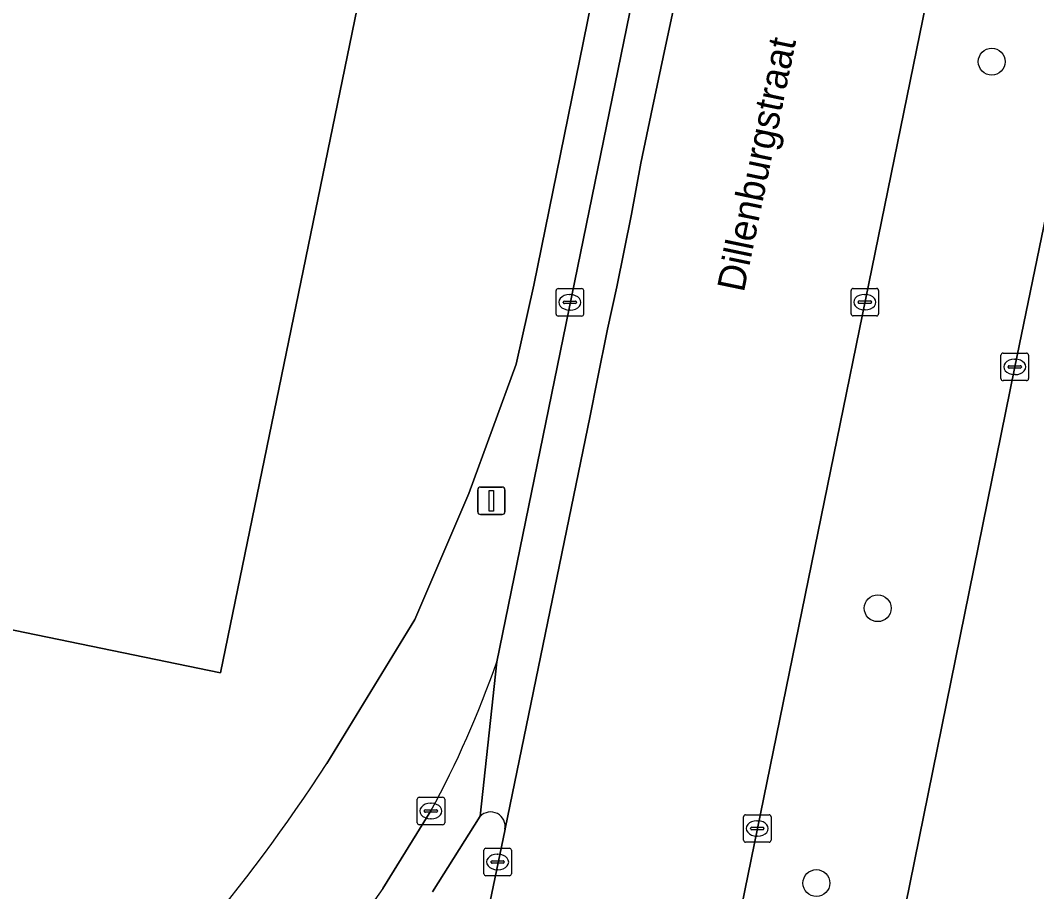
# Model space of a CAD drawing. Extents: x 157692 to 159674, y 381452 to 383291.
# Drawn here: x 158498.72 to 158535.67, y 382148.13 to 382179.81 of the extents above; entities that cross this region are included whole.
import ezdxf

# ---------------------------------------------------------------- set-up
doc = ezdxf.new("R2010")
doc.units = 0
for name, color, linetype in [('IMGEO_Berm_groen', 7, 'Continuous'), ('IMGEO_Boom', 7, 'Continuous'), ('IMGEO_Erf', 7, 'Continuous'), ('IMGEO_Fietspad_gesloten', 7, 'Continuous'), ('IMGEO_Kolk', 7, 'Continuous'), ('IMGEO_Lichtmast', 7, 'Continuous'), ('IMGEO_Openbare_ruimte_label', 7, 'Continuous'), ('IMGEO_Pand', 7, 'Continuous'), ('IMGEO_Rijbaan_lokaal_gesloten', 7, 'Continuous'), ('IMGEO_Verkeerseiland_groen', 7, 'Continuous'), ('IMGEO_Voetpad_open', 7, 'Continuous')]:
    doc.layers.add(name, color=color, linetype=linetype)

msp = doc.modelspace()

# ---------------------------------------------------------------- linework, layer by layer
at = {"layer": 'IMGEO_Berm_groen'}
for points in [[(158566.644, 382322.187), (158567.234, 382325.064), (158567.304, 382325.746), (158567.225, 382326.384), (158567.068, 382326.86), (158566.787, 382327.371), (158566.493, 382327.735), (158566.011, 382328.143), (158565.497, 382328.42), (158565.051, 382328.557), (158564.939, 382328.591), (158564.425, 382328.647), (158563.854, 382328.604), (158563.281, 382328.442), (158562.742, 382328.162), (158562.266, 382327.772), (158561.897, 382327.314), (158561.609, 382326.746), (158561.45, 382326.139), (158553.124, 382285.066), (158549.349, 382267.06), (158522.982, 382137.975)], [(158528.747, 382136.998), (158534.877, 382167.21), (158542.075, 382202.135), (158547.202, 382227.455), (158566.644, 382322.187)]]:
    msp.add_lwpolyline(points, dxfattribs=at)
at = {"layer": 'IMGEO_Boom'}
for centre in [(158534.04, 382178.306), (158529.896, 382158.438), (158527.666, 382148.444)]:
    msp.add_circle(centre, 0.489, dxfattribs=at)
at = {"layer": 'IMGEO_Erf'}
for points in [[(158509.861, 382152.794), (158513.065, 382158.027), (158515.032, 382162.604), (158516.746, 382167.312), (158517.398, 382170.178), (158524.332, 382204.307), (158524.967, 382207.431), (158524.987, 382207.53), (158526.326, 382214.089), (158527.009, 382217.437), (158528.187, 382223.205), (158528.445, 382224.468), (158549.165, 382325.299), (158550.563, 382332.1), (158550.799, 382333.648), (158551.524, 382338.412)], [(158464.768, 382230.207), (158518.944, 382219.046), (158505.997, 382156.09), (158482, 382161.038), (158467.988, 382163.933), (158454.893, 382166.763)]]:
    msp.add_lwpolyline(points, dxfattribs=at)
msp.add_arc((158459.249, 382185.395), 60.203, 311.86075, 327.21256, dxfattribs=at)
at = {"layer": 'IMGEO_Fietspad_gesloten'}
for points in [[(158513.708, 382148.133), (158515.441, 382150.872), (158516.046, 382156.484)], [(158513.651, 382151.066), (158511.906, 382148.246)]]:
    msp.add_lwpolyline(points, dxfattribs=at)
for centre, radius, start, end in [((158481.088, 382168.699), 37.03, 331.5647, 340.7401), ((158524.385, 382139.071), 15.489, 143.6738, 173.4818)]:
    msp.add_arc(centre, radius, start, end, dxfattribs=at)
at = {"layer": 'IMGEO_Kolk'}
for p, q in [((158518.203, 382169.132), (158518.203, 382169.984)), ((158518.278, 382170.058), (158519.13, 382170.058)), ((158519.204, 382169.984), (158519.204, 382169.132)), ((158528.926, 382169.138), (158528.926, 382169.99)), ((158529.001, 382170.064), (158529.853, 382170.064)), ((158529.927, 382169.99), (158529.927, 382169.138)), ((158518.462, 382169.552), (158518.462, 382169.564)), ((158518.9, 382169.515), (158518.502, 382169.515)), ((158518.505, 382169.601), (158518.903, 382169.601)), ((158518.691, 382169.838), (158518.716, 382169.838)), ((158518.946, 382169.564), (158518.946, 382169.552)), ((158529.185, 382169.558), (158529.185, 382169.57)), ((158529.623, 382169.521), (158529.225, 382169.521)), ((158529.228, 382169.607), (158529.626, 382169.607)), ((158529.414, 382169.844), (158529.439, 382169.844)), ((158529.669, 382169.57), (158529.669, 382169.558)), ((158518.714, 382169.278), (158518.689, 382169.278)), ((158529.437, 382169.284), (158529.412, 382169.284)), ((158519.13, 382169.058), (158518.278, 382169.058)), ((158529.853, 382169.064), (158529.001, 382169.064)), ((158534.376, 382166.784), (158534.376, 382167.636)), ((158534.451, 382167.71), (158535.303, 382167.71)), ((158535.377, 382167.636), (158535.377, 382166.784)), ((158534.864, 382167.49), (158534.889, 382167.49)), ((158534.635, 382167.204), (158534.635, 382167.216)), ((158535.073, 382167.167), (158534.675, 382167.167)), ((158534.678, 382167.253), (158535.076, 382167.253)), ((158534.887, 382166.93), (158534.862, 382166.93)), ((158535.119, 382167.216), (158535.119, 382167.204)), ((158535.303, 382166.71), (158534.451, 382166.71)), ((158513.15, 382150.64), (158513.15, 382151.492)), ((158513.225, 382151.566), (158514.077, 382151.566)), ((158514.151, 382151.492), (158514.151, 382150.64)), ((158513.409, 382151.06), (158513.409, 382151.072)), ((158513.847, 382151.023), (158513.449, 382151.023)), ((158513.452, 382151.109), (158513.85, 382151.109)), ((158513.638, 382151.346), (158513.663, 382151.346)), ((158513.893, 382151.072), (158513.893, 382151.06)), ((158513.661, 382150.786), (158513.636, 382150.786)), ((158525.016, 382150.004), (158525.016, 382150.856)), ((158525.091, 382150.93), (158525.943, 382150.93)), ((158525.504, 382150.71), (158525.529, 382150.71)), ((158526.017, 382150.856), (158526.017, 382150.004)), ((158514.077, 382150.566), (158513.225, 382150.566)), ((158525.275, 382150.424), (158525.275, 382150.436)), ((158525.713, 382150.387), (158525.315, 382150.387)), ((158525.318, 382150.473), (158525.716, 382150.473)), ((158525.759, 382150.436), (158525.759, 382150.424)), ((158525.943, 382149.93), (158525.091, 382149.93)), ((158525.527, 382150.15), (158525.502, 382150.15)), ((158515.576, 382148.785), (158515.576, 382149.637)), ((158515.651, 382149.711), (158516.503, 382149.711)), ((158516.577, 382149.637), (158516.577, 382148.785)), ((158515.835, 382149.205), (158515.835, 382149.217)), ((158516.273, 382149.168), (158515.875, 382149.168)), ((158515.878, 382149.254), (158516.276, 382149.254)), ((158516.064, 382149.491), (158516.089, 382149.491)), ((158516.319, 382149.217), (158516.319, 382149.205)), ((158516.087, 382148.931), (158516.062, 382148.931)), ((158516.503, 382148.711), (158515.651, 382148.711))]:
    msp.add_line(p, q, dxfattribs=at)
for points in [[(158518.203, 382169.132), (158518.203, 382169.984)], [(158518.278, 382170.058), (158519.13, 382170.058)], [(158519.204, 382169.984), (158519.204, 382169.132)], [(158528.926, 382169.138), (158528.926, 382169.99)], [(158529.001, 382170.064), (158529.853, 382170.064)], [(158529.927, 382169.99), (158529.927, 382169.138)], [(158519.13, 382169.058), (158518.278, 382169.058)], [(158529.853, 382169.064), (158529.001, 382169.064)], [(158534.376, 382166.784), (158534.376, 382167.636)], [(158534.451, 382167.71), (158535.303, 382167.71)], [(158535.377, 382167.636), (158535.377, 382166.784)], [(158535.303, 382166.71), (158534.451, 382166.71)], [(158513.15, 382150.64), (158513.15, 382151.492)], [(158513.225, 382151.566), (158514.077, 382151.566)], [(158514.151, 382151.492), (158514.151, 382150.64)], [(158525.016, 382150.004), (158525.016, 382150.856)], [(158525.091, 382150.93), (158525.943, 382150.93)], [(158526.017, 382150.856), (158526.017, 382150.004)], [(158514.077, 382150.566), (158513.225, 382150.566)], [(158525.943, 382149.93), (158525.091, 382149.93)], [(158515.576, 382148.785), (158515.576, 382149.637)], [(158515.651, 382149.711), (158516.503, 382149.711)], [(158516.577, 382149.637), (158516.577, 382148.785)], [(158516.503, 382148.711), (158515.651, 382148.711)]]:
    msp.add_lwpolyline(points, dxfattribs=at)
for centre, radius, start, end in [((158518.28, 382169.982), 0.0765, 91.552, 178.448), ((158518.28, 382169.982), 0.0765, 91.552, 178.448), ((158519.128, 382169.982), 0.0765, 1.552, 88.448), ((158519.128, 382169.982), 0.0765, 1.552, 88.448), ((158529.003, 382169.988), 0.0765, 91.552, 178.448), ((158529.003, 382169.988), 0.0765, 91.552, 178.448), ((158529.851, 382169.988), 0.0765, 1.552, 88.448), ((158529.851, 382169.988), 0.0765, 1.552, 88.448), ((158518.502, 382169.561), 0.0403, 85.8775, 175.7526), ((158518.499, 382169.551), 0.0366, 178.938, 274.7102), ((158518.903, 382169.558), 0.043, 264.8664, 352.4533), ((158518.907, 382169.563), 0.0386, 1.7309, 96.639), ((158529.225, 382169.567), 0.0403, 85.8775, 175.7526), ((158529.222, 382169.557), 0.0366, 178.938, 274.7102), ((158529.626, 382169.564), 0.043, 264.8664, 352.4533), ((158529.63, 382169.569), 0.0386, 1.7309, 96.639), ((158518.28, 382169.134), 0.0765, 181.552, 268.448), ((158518.28, 382169.134), 0.0765, 181.552, 268.448), ((158519.128, 382169.134), 0.0765, 271.552, 358.448), ((158519.128, 382169.134), 0.0765, 271.552, 358.448), ((158529.003, 382169.14), 0.0765, 181.552, 268.448), ((158529.003, 382169.14), 0.0765, 181.552, 268.448), ((158529.851, 382169.14), 0.0765, 271.552, 358.448), ((158529.851, 382169.14), 0.0765, 271.552, 358.448), ((158534.453, 382167.634), 0.0765, 91.552, 178.448), ((158534.453, 382167.634), 0.0765, 91.552, 178.448), ((158535.301, 382167.634), 0.0765, 1.552, 88.448), ((158535.301, 382167.634), 0.0765, 1.552, 88.448), ((158534.675, 382167.213), 0.0403, 85.8775, 175.7526), ((158534.672, 382167.203), 0.0366, 178.938, 274.7102), ((158535.076, 382167.21), 0.043, 264.8664, 352.4533), ((158535.08, 382167.215), 0.0386, 1.7309, 96.639), ((158534.453, 382166.786), 0.0765, 181.552, 268.448), ((158534.453, 382166.786), 0.0765, 181.552, 268.448), ((158535.301, 382166.786), 0.0765, 271.552, 358.448), ((158535.301, 382166.786), 0.0765, 271.552, 358.448), ((158513.227, 382151.49), 0.0765, 91.552, 178.448), ((158513.227, 382151.49), 0.0765, 91.552, 178.448), ((158514.075, 382151.49), 0.0765, 1.552, 88.448), ((158514.075, 382151.49), 0.0765, 1.552, 88.448), ((158513.449, 382151.069), 0.0403, 85.8775, 175.7526), ((158513.446, 382151.059), 0.0366, 178.938, 274.7102), ((158513.85, 382151.066), 0.043, 264.8664, 352.4533), ((158513.854, 382151.071), 0.0386, 1.7309, 96.639), ((158513.227, 382150.642), 0.0765, 181.552, 268.448), ((158513.227, 382150.642), 0.0765, 181.552, 268.448), ((158514.075, 382150.642), 0.0765, 271.552, 358.448), ((158514.075, 382150.642), 0.0765, 271.552, 358.448), ((158525.093, 382150.854), 0.0765, 91.552, 178.448), ((158525.093, 382150.854), 0.0765, 91.552, 178.448), ((158525.941, 382150.854), 0.0765, 1.552, 88.448), ((158525.941, 382150.854), 0.0765, 1.552, 88.448), ((158525.315, 382150.433), 0.0403, 85.8775, 175.7526), ((158525.312, 382150.423), 0.0366, 178.938, 274.7102), ((158525.716, 382150.43), 0.043, 264.8664, 352.4533), ((158525.72, 382150.435), 0.0386, 1.7309, 96.639), ((158525.093, 382150.006), 0.0765, 181.552, 268.448), ((158525.093, 382150.006), 0.0765, 181.552, 268.448), ((158525.941, 382150.006), 0.0765, 271.552, 358.448), ((158525.941, 382150.006), 0.0765, 271.552, 358.448), ((158515.653, 382149.635), 0.0765, 91.552, 178.448), ((158515.653, 382149.635), 0.0765, 91.552, 178.448), ((158516.501, 382149.635), 0.0765, 1.552, 88.448), ((158516.501, 382149.635), 0.0765, 1.552, 88.448), ((158515.875, 382149.214), 0.0403, 85.8775, 175.7526), ((158515.872, 382149.204), 0.0366, 178.938, 274.7102), ((158516.276, 382149.211), 0.043, 264.8664, 352.4533), ((158516.28, 382149.216), 0.0386, 1.7309, 96.639), ((158515.653, 382148.787), 0.0765, 181.552, 268.448), ((158515.653, 382148.787), 0.0765, 181.552, 268.448), ((158516.501, 382148.787), 0.0765, 271.552, 358.448), ((158516.501, 382148.787), 0.0765, 271.552, 358.448)]:
    msp.add_arc(centre, radius, start, end, dxfattribs=at)
for centre, major_axis, ratio, start_param, end_param in [((158518.69, 382169.558), (-0.387, 0.002), 0.722429, 4.712389, 7.853982), ((158518.715, 382169.558), (-0.39, 0.002), 0.717154, 1.570796, 4.712389), ((158529.413, 382169.564), (-0.387, 0.002), 0.722429, 4.712389, 7.853982), ((158529.438, 382169.564), (-0.39, 0.002), 0.717154, 1.570796, 4.712389), ((158534.863, 382167.21), (-0.387, 0.002), 0.722429, 4.712389, 7.853982), ((158534.888, 382167.21), (-0.39, 0.002), 0.717154, 1.570796, 4.712389), ((158513.637, 382151.066), (-0.387, 0.002), 0.722429, 4.712389, 7.853982), ((158513.662, 382151.066), (-0.39, 0.002), 0.717154, 1.570796, 4.712389), ((158525.503, 382150.43), (-0.387, 0.002), 0.722429, 4.712389, 7.853982), ((158525.528, 382150.43), (-0.39, 0.002), 0.717154, 1.570796, 4.712389), ((158516.063, 382149.211), (-0.387, 0.002), 0.722429, 4.712389, 7.853982), ((158516.088, 382149.211), (-0.39, 0.002), 0.717154, 1.570796, 4.712389)]:
    msp.add_ellipse(centre, major_axis=major_axis, ratio=ratio, start_param=start_param, end_param=end_param, dxfattribs=at)
at = {"layer": 'IMGEO_Lichtmast'}
for p, q in [((158515.453, 382162.844), (158516.243, 382162.844)), ((158516.243, 382162.844), (158515.453, 382162.844)), ((158515.353, 382161.944), (158515.353, 382162.744)), ((158515.353, 382162.744), (158515.353, 382161.944)), ((158516.343, 382162.744), (158516.343, 382161.944)), ((158516.343, 382161.944), (158516.343, 382162.744)), ((158516.243, 382161.844), (158515.453, 382161.844)), ((158515.453, 382161.844), (158516.243, 382161.844))]:
    msp.add_line(p, q, dxfattribs=at)
msp.add_lwpolyline([(158515.773, 382162.719), (158515.923, 382162.719), (158515.923, 382161.969), (158515.773, 382161.969), (158515.773, 382162.719)], dxfattribs=at)
for centre, start, end in [((158515.453, 382162.744), 90, 180), ((158515.453, 382162.744), 90, 180), ((158516.243, 382162.744), 0, 90), ((158516.243, 382162.744), 360, 90), ((158515.453, 382161.944), 180, 270), ((158515.453, 382161.944), 180, 270), ((158516.243, 382161.944), 270, 0), ((158516.243, 382161.944), 270, 0)]:
    msp.add_arc(centre, 0.1, start, end, dxfattribs=at)
at = {"layer": 'IMGEO_Pand'}
msp.add_lwpolyline([(158454.893, 382166.763), (158467.988, 382163.933), (158482, 382161.038), (158505.997, 382156.09), (158518.944, 382219.046), (158464.768, 382230.207)], dxfattribs=at)
at = {"layer": 'IMGEO_Rijbaan_lokaal_gesloten'}
for points in [[(158566.717, 382304.975), (158570.119, 382321.454), (158566.644, 382322.187), (158547.202, 382227.455), (158542.075, 382202.135), (158534.877, 382167.21), (158528.747, 382136.998), (158534.64, 382136.161), (158544.988, 382186.707), (158554.178, 382231.666)], [(158522.982, 382137.975), (158549.349, 382267.06)], [(158516.345, 382150.4), (158516.351, 382150.416), (158519.44, 382165.43), (158519.695, 382166.711), (158520.067, 382168.58), (158520.406, 382170.124), (158520.949, 382172.76), (158521.285, 382174.615), (158521.711, 382176.637), (158522.095, 382178.467), (158522.54, 382180.58), (158522.925, 382182.414), (158523.324, 382184.31), (158523.361, 382184.485), (158523.847, 382186.302), (158524.097, 382187.038), (158524.398, 382187.848), (158525.073, 382189.43), (158525.289, 382189.937), (158525.428, 382190.17), (158526.611, 382192.236), (158527.621, 382193.95), (158528.593, 382195.516), (158541.544, 382258.661)], [(158525.939, 382194.629), (158522.444, 382187.753), (158516.046, 382156.484), (158515.441, 382150.872)], [(158522.54, 382180.58), (158522.095, 382178.467), (158521.711, 382176.637), (158521.285, 382174.615), (158520.949, 382172.76), (158520.406, 382170.124), (158520.067, 382168.58), (158519.695, 382166.711), (158519.44, 382165.43), (158516.351, 382150.416), (158516.345, 382150.4), (158514.093, 382139.59)]]:
    msp.add_lwpolyline(points, dxfattribs=at)
msp.add_arc((158515.82, 382150.497), 0.533, 349.5318, 135.3279, dxfattribs=at)
at = {"layer": 'IMGEO_Verkeerseiland_groen'}
for points in [[(158515.441, 382150.872), (158513.708, 382148.133)], [(158514.093, 382139.59), (158516.345, 382150.4)]]:
    msp.add_lwpolyline(points, dxfattribs=at)
msp.add_arc((158515.82, 382150.497), 0.533, 349.5318, 135.3279, dxfattribs=at)
at = {"layer": 'IMGEO_Voetpad_open'}
for points in [[(158526.501, 382196.114), (158528.224, 382204.425), (158524.987, 382207.53), (158524.967, 382207.431), (158524.332, 382204.307), (158517.398, 382170.178), (158516.746, 382167.312), (158515.032, 382162.604), (158513.065, 382158.027), (158509.861, 382152.794)], [(158516.046, 382156.484), (158522.444, 382187.753), (158525.939, 382194.629)], [(158511.906, 382148.246), (158513.651, 382151.066)]]:
    msp.add_lwpolyline(points, dxfattribs=at)
for centre, radius, start, end in [((158481.088, 382168.699), 37.03, 331.5647, 340.7401), ((158459.249, 382185.395), 60.203, 311.86075, 327.21256), ((158524.385, 382139.071), 15.489, 143.6738, 173.4818)]:
    msp.add_arc(centre, radius, start, end, dxfattribs=at)

# ---------------------------------------------------------------- texts
at = {"layer": 'IMGEO_Openbare_ruimte_label'}
msp.add_text('Dillenburgstraat', height=1, rotation=78.2855, dxfattribs=at).set_placement((158525.026, 382169.893))

doc.saveas('drawing.dxf')
